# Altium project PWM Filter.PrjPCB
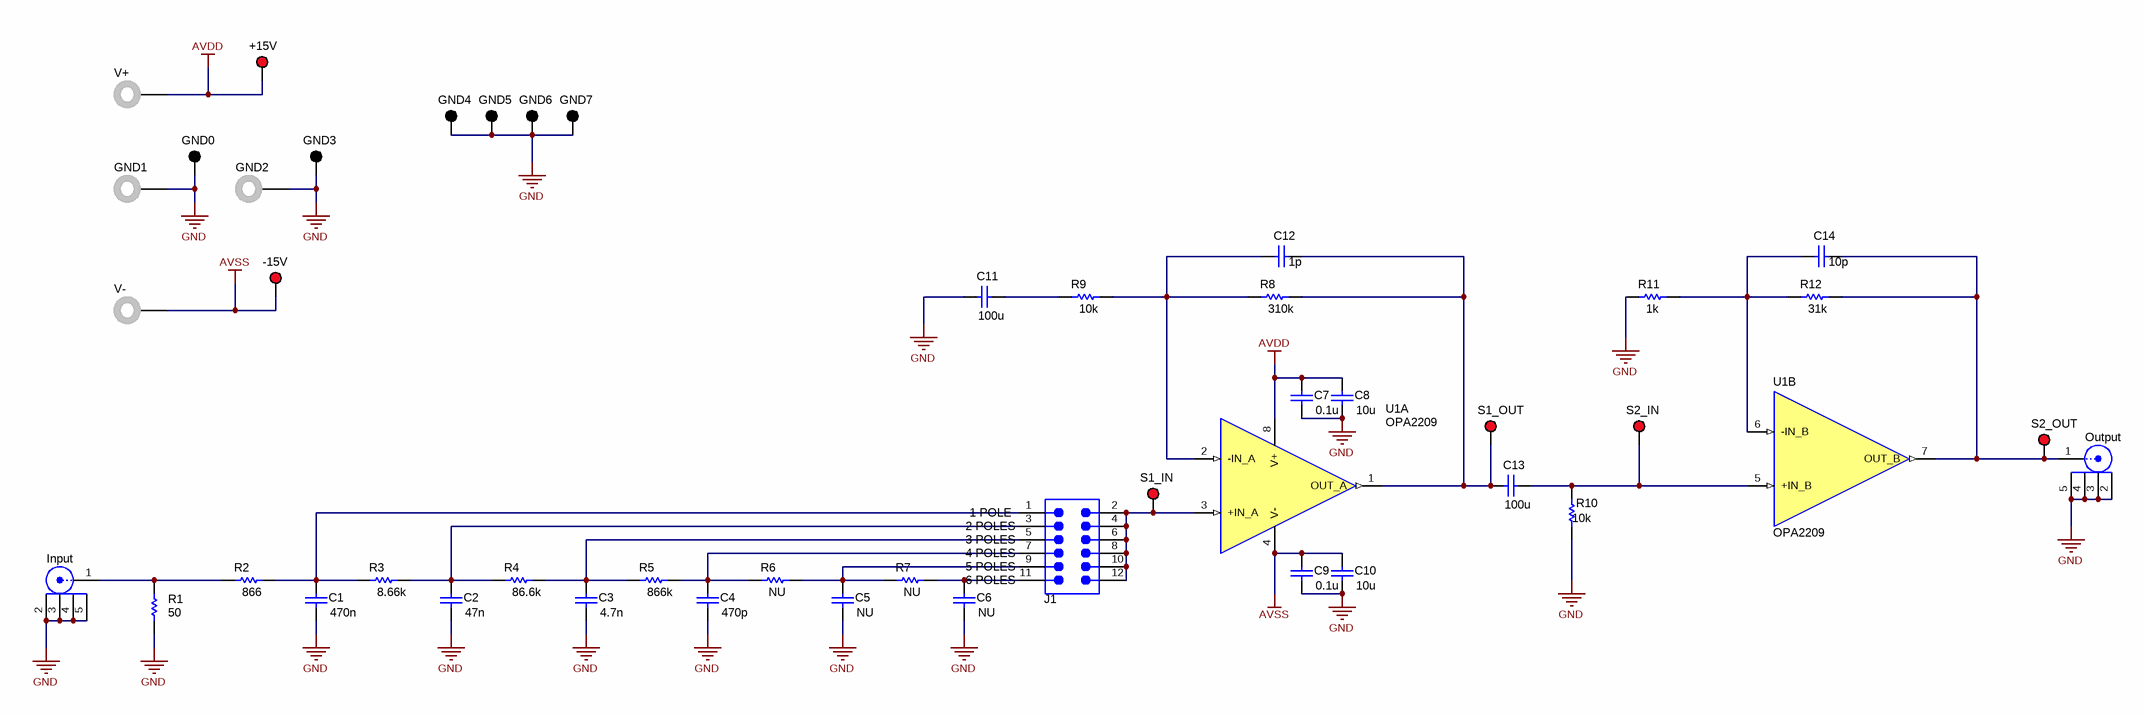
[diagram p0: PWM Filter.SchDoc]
CopyrightYear: 2012; PCB_Layout: Who did the Layout?; PCB_Rev: E1; PRJ_Customer: Public Release; PRJ_Engineer: Enter name of project lead; PRJ_Number: XX####; PRJ_Title: Change in menu Project|Project Options|Parameters; SCH_Rev: E1; TechSupport: http://www.ti.com/support
1 sheet, 46 parts. Net scope: global (net labels, ports and power ports of the same name join across sheets).
Board file: PWM Filter.PcbDoc

## Sheet PWM Filter.SchDoc
size 431 x 279 mm; Date: Not shown in title block; ApprovedBy: Not shown in title block; CheckedBy: Not shown in title block; Author: Not shown in title block; CompanyName: Not shown in title block; Engineer: Not shown in title block; Organization: Not shown in title block; Address1: Not shown in title block; Address2: Not shown in title block; Address3: Not shown in title block; Address4: Not shown in title block; DocumentNumber: 1; Revision: Use project parameter SCH_Rev; SheetNumber: 1; SheetTotal: 1; PageSetup: Record=PageOptions|CenterHorizontal=True|CenterVertical=True|PrintScale=1.00|XCorrection=1.00|YCorrection=1.00|PrintKind=0|BorderSize=5000000|LeftOffset=0|BottomOffset=0|Orientation=2|PaperLength=1000|PaperWidth=1000|Scale=100|PaperSource=15|PrintQuality=600|MediaType=1|DitherType=10|PaperKind=Letter|PrintScaleMode=1

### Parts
+15V  5000  [Keystone5000]  (value not drawn)
-15V  5000  [Keystone5000]  (value not drawn)
C1  470n  [1210]
C2  47n  [1210]
C3  4.7n  [1210]
C4  470p  [1210]
C5  NU  [1210]
C6  NU  [1210]
C7  0.1u  [0603]
C8  10u  [1210]
C9  0.1u  [0603]
C10  10u  [1210]
C11  100u  [1210]
C12  1p  [0603]
C13  100u  [1210]
C14  10p  [0603]
GND0  5001  [Keystone5001]  (value not drawn)
GND1  108-0740-001  [Johnson_108-0740-001]  (value not drawn)
GND2  108-0740-001  [Johnson_108-0740-001]  (value not drawn)
GND3  5001  [Keystone5001]  (value not drawn)
GND4  5001  [Keystone5001]  (value not drawn)
GND5  5001  [Keystone5001]  (value not drawn)
GND6  5001  [Keystone5001]  (value not drawn)
GND7  5001  [Keystone5001]  (value not drawn)
Input  901-143  [Amphenol_901-143]  (value not drawn)
J1  TSW-106-07-G-D  [TSW-106-07-G-D]  (value not drawn)
Output  901-143  [Amphenol_901-143]  (value not drawn)
R1  50  [0603]
R2  866  [0603]
R3  8.66k  [0603]
R4  86.6k  [0603]
R5  866k  [0603]
R6  NU  [0603]
R7  NU  [0603]
R8  310k  [0603]
R9  10k  [0603]
R10  10k  [0603]
R11  1k  [0603]
R12  31k  [0603]
S1_IN  5000  [Keystone5000]  (value not drawn)
S1_OUT  5000  [Keystone5000]  (value not drawn)
S2_IN  5000  [Keystone5000]  (value not drawn)
S2_OUT  5000  [Keystone5000]  (value not drawn)
U1  OPA2209  [D0008A_M]  (parts A,B of 2)
V+  108-0740-001  [Johnson_108-0740-001]  (value not drawn)
V-  108-0740-001  [Johnson_108-0740-001]  (value not drawn)

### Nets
AVDD: +15V.1 C7.1 C8.1 U1.8(V+) V+.1
AVSS: -15V.1 C9.1 C10.1 U1.4(V-) V-.1
GND: C1.2 C2.2 C3.2 C4.2 C5.2 C6.2 C7.2 C8.2 C9.2 C10.2 C11.2 GND0.1 GND1.1 GND2.1 GND3.1 GND4.1 GND5.1 GND6.1 GND7.1 Input.2 Input.3 Input.4 Input.5 Output.2 Output.3 Output.4 Output.5 R1.1 R10.1 R11.1
NetC1_1: C1.1 J1.1 R2.2 R3.1
NetC2_1: C2.1 J1.3 R3.2 R4.1
NetC3_1: C3.1 J1.5 R4.2 R5.1
NetC4_1: C4.1 J1.7 R5.2 R6.1
NetC5_1: C5.1 J1.9 R6.2 R7.1
NetC6_1: C6.1 J1.11 R7.2
NetC11_1: C11.1 R9.1
NetC12_1: C12.1 C13.2 R8.2 S1_OUT.1 U1.1(OUT_A)
NetC12_2: C12.2 R8.1 R9.2 U1.2(-IN_A)
NetC13_1: C13.1 R10.2 S2_IN.1 U1.5(+IN_B)
NetC14_1: C14.1 Output.1 R12.2 S2_OUT.1 U1.7(OUT_B)
NetC14_2: C14.2 R11.2 R12.1 U1.6(-IN_B)
NetInput_1: Input.1 R1.2 R2.1
NetJ1_2: J1.2 J1.4 J1.6 J1.8 J1.10 J1.12 S1_IN.1 U1.3(+IN_A)

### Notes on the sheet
- (near J1) 1 POLE
- (near J1) 2 POLES
- 3 POLES
- 4 POLES
- 5 POLES
- (near C6) 6 POLES

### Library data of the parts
+15V -15V S1_IN S1_OUT S2_IN S2_OUT = 5000: Test Point, TH, Miniature, Red; Manufacturer: Keystone; CompType: Test Point Loop; U/M: EA
C1-C14 = Capacitor: CAP, CERM, xxxF, xxV, [TempCo], xx%, [PackageReference]; Manufacturer: Used in BOM report; Polarized: N; U/M: EA
GND0 GND3-GND7 = 5001: Test Point, TH, Miniature, Black; Manufacturer: Keystone; CompType: Test Point Loop; U/M: EA
GND1 GND2 V+ V- = 108-0740-001: Standard Banana Jack, Uninsulated, 15A; Manufacturer: Emerson Network Power; SymbolCreator: a0412235; CompType: Connector; U/M: EA
Input Output = 901-143: Connector, TH, Right Angle SMA 50 ohm; Manufacturer: Amphenol RF; Value: 50 Ohm; U/M: EA
J1 = TSW-106-07-G-D: Header, TH, 100mil, 6x2, Gold plated, 230 mil above insulator; Manufacturer: Samtec, Inc.; U/M: EA
R1-R12 = Resistor: RES, xxx ohm, x%, xW, [PackageReference]; Manufacturer: Used in BOM report; U/M: EA
U1 = OPA2188: Manufacturer: Used in BOM report; SymbolVersion: use current date i.e. 2008-05-20; SymbolCreator: Use a-id; CompType: Used in some BOM reports.  Useful for finding later.; U/M: EA, IN, or GM

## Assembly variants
001: all parts fitted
